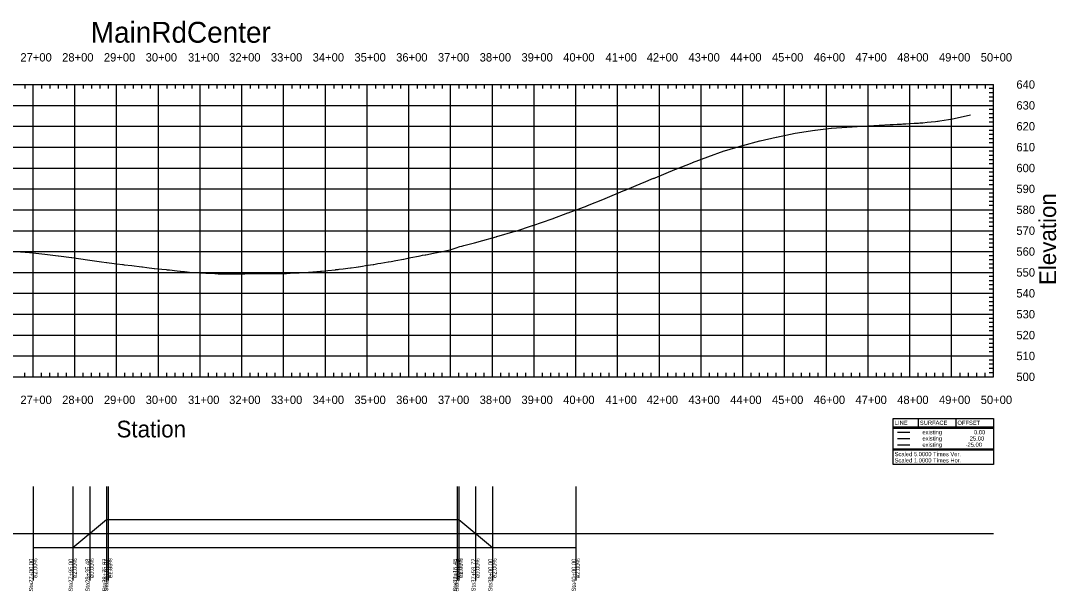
# Model space of a CAD drawing. Extents: x 708103 to 717568, y 374476 to 378707.
# Drawn here: x 709989 to 712470, y 374476 to 375842 of the extents above; entities that cross this region are included whole.
import ezdxf

# ---------------------------------------------------------------- set-up
doc = ezdxf.new("R2010")
doc.units = 0
for name, color, linetype in [('1', 7, 'Continuous'), ('54', 7, 'Continuous'), ('61', 7, 'Continuous'), ('63', 7, 'Continuous'), ('Existing', 7, 'Continuous')]:
    doc.layers.add(name, color=color, linetype=linetype)

msp = doc.modelspace()

# ---------------------------------------------------------------- linework, layer by layer
for points in [[(710019, 374581.2), (710114, 374581.2), (710195, 374648.4), (711038.5, 374648.4), (711119, 374581.2), (711319, 374581.2)], [(708319, 374614.8), (712319, 374614.8)], [(710019, 374581.2), (711319, 374581.2)]]:
    msp.add_lwpolyline(points)
at = {"layer": '54'}
for points in [[(710019, 374727.3), (710019, 374502.3)], [(710114, 374727.3), (710114, 374502.3)], [(710154.5, 374727.3), (710154.5, 374502.3)], [(710195, 374727.3), (710195, 374502.3)], [(710199, 374727.3), (710199, 374502.3)], [(711034.5, 374727.3), (711034.5, 374502.3)], [(711038.5, 374727.3), (711038.5, 374502.3)], [(711078.7, 374727.3), (711078.7, 374502.3)], [(711119, 374727.3), (711119, 374502.3)], [(711319, 374727.3), (711319, 374502.3)]]:
    msp.add_lwpolyline(points, dxfattribs=at)
at = {"layer": '61'}
for p, q in [((708319, 375689.8), (712319, 375689.8)), ((709999, 375689.8), (709999, 375679.8)), ((710019, 374989.8), (710019, 375689.8)), ((710039, 375689.8), (710039, 375679.8)), ((710059, 375689.8), (710059, 375679.8)), ((710079, 375689.8), (710079, 375679.8)), ((710099, 375689.8), (710099, 375679.8)), ((710119, 374989.8), (710119, 375689.8)), ((710139, 375689.8), (710139, 375679.8)), ((710159, 375689.8), (710159, 375679.8)), ((710179, 375689.8), (710179, 375679.8)), ((710199, 375689.8), (710199, 375679.8)), ((710219, 374989.8), (710219, 375689.8)), ((710239, 375689.8), (710239, 375679.8)), ((710259, 375689.8), (710259, 375679.8)), ((710279, 375689.8), (710279, 375679.8)), ((710299, 375689.8), (710299, 375679.8)), ((710319, 374989.8), (710319, 375689.8)), ((710339, 375689.8), (710339, 375679.8)), ((710359, 375689.8), (710359, 375679.8)), ((710379, 375689.8), (710379, 375679.8)), ((710399, 375689.8), (710399, 375679.8)), ((710419, 374989.8), (710419, 375689.8)), ((710439, 375689.8), (710439, 375679.8)), ((710459, 375689.8), (710459, 375679.8)), ((710479, 375689.8), (710479, 375679.8)), ((710499, 375689.8), (710499, 375679.8)), ((710519, 374989.8), (710519, 375689.8)), ((710539, 375689.8), (710539, 375679.8)), ((710559, 375689.8), (710559, 375679.8)), ((710579, 375689.8), (710579, 375679.8)), ((710599, 375689.8), (710599, 375679.8)), ((710619, 374989.8), (710619, 375689.8)), ((710639, 375689.8), (710639, 375679.8)), ((710659, 375689.8), (710659, 375679.8)), ((710679, 375689.8), (710679, 375679.8)), ((710699, 375689.8), (710699, 375679.8)), ((710719, 374989.8), (710719, 375689.8)), ((710739, 375689.8), (710739, 375679.8)), ((710759, 375689.8), (710759, 375679.8)), ((710779, 375689.8), (710779, 375679.8)), ((710799, 375689.8), (710799, 375679.8)), ((710819, 374989.8), (710819, 375689.8)), ((710839, 375689.8), (710839, 375679.8)), ((710859, 375689.8), (710859, 375679.8)), ((710879, 375689.8), (710879, 375679.8)), ((710899, 375689.8), (710899, 375679.8)), ((710919, 374989.8), (710919, 375689.8)), ((710939, 375689.8), (710939, 375679.8)), ((710959, 375689.8), (710959, 375679.8)), ((710979, 375689.8), (710979, 375679.8)), ((710999, 375689.8), (710999, 375679.8)), ((711019, 374989.8), (711019, 375689.8)), ((711039, 375689.8), (711039, 375679.8)), ((711059, 375689.8), (711059, 375679.8)), ((711079, 375689.8), (711079, 375679.8)), ((711099, 375689.8), (711099, 375679.8)), ((711119, 374989.8), (711119, 375689.8)), ((711139, 375689.8), (711139, 375679.8)), ((711159, 375689.8), (711159, 375679.8)), ((711179, 375689.8), (711179, 375679.8)), ((711199, 375689.8), (711199, 375679.8)), ((711219, 374989.8), (711219, 375689.8)), ((711239, 375689.8), (711239, 375679.8)), ((711259, 375689.8), (711259, 375679.8)), ((711279, 375689.8), (711279, 375679.8)), ((711299, 375689.8), (711299, 375679.8)), ((711319, 374989.8), (711319, 375689.8)), ((711339, 375689.8), (711339, 375679.8)), ((711359, 375689.8), (711359, 375679.8)), ((711379, 375689.8), (711379, 375679.8)), ((711399, 375689.8), (711399, 375679.8)), ((711419, 374989.8), (711419, 375689.8)), ((711439, 375689.8), (711439, 375679.8)), ((711459, 375689.8), (711459, 375679.8)), ((711479, 375689.8), (711479, 375679.8)), ((711499, 375689.8), (711499, 375679.8)), ((711519, 374989.8), (711519, 375689.8)), ((711539, 375689.8), (711539, 375679.8)), ((711559, 375689.8), (711559, 375679.8)), ((711579, 375689.8), (711579, 375679.8)), ((711599, 375689.8), (711599, 375679.8)), ((711619, 374989.8), (711619, 375689.8)), ((711639, 375689.8), (711639, 375679.8)), ((711659, 375689.8), (711659, 375679.8)), ((711679, 375689.8), (711679, 375679.8)), ((711699, 375689.8), (711699, 375679.8)), ((711719, 374989.8), (711719, 375689.8)), ((711739, 375689.8), (711739, 375679.8)), ((711759, 375689.8), (711759, 375679.8)), ((711779, 375689.8), (711779, 375679.8)), ((711799, 375689.8), (711799, 375679.8)), ((711819, 374989.8), (711819, 375689.8)), ((711839, 375689.8), (711839, 375679.8)), ((711859, 375689.8), (711859, 375679.8)), ((711879, 375689.8), (711879, 375679.8)), ((711899, 375689.8), (711899, 375679.8)), ((711919, 374989.8), (711919, 375689.8)), ((711939, 375689.8), (711939, 375679.8)), ((711959, 375689.8), (711959, 375679.8)), ((711979, 375689.8), (711979, 375679.8)), ((711999, 375689.8), (711999, 375679.8)), ((712019, 374989.8), (712019, 375689.8)), ((712039, 375689.8), (712039, 375679.8)), ((712059, 375689.8), (712059, 375679.8)), ((712079, 375689.8), (712079, 375679.8)), ((712099, 375689.8), (712099, 375679.8)), ((712119, 374989.8), (712119, 375689.8)), ((712139, 375689.8), (712139, 375679.8)), ((712159, 375689.8), (712159, 375679.8)), ((712179, 375689.8), (712179, 375679.8)), ((712199, 375689.8), (712199, 375679.8)), ((712219, 374989.8), (712219, 375689.8)), ((712239, 375689.8), (712239, 375679.8)), ((712259, 375689.8), (712259, 375679.8)), ((712279, 375689.8), (712279, 375679.8)), ((712299, 375689.8), (712299, 375679.8)), ((712319, 374989.8), (712319, 375689.8)), ((712319, 375679.8), (712309, 375679.8)), ((712319, 375669.8), (712309, 375669.8)), ((712319, 375659.8), (712309, 375659.8)), ((708319, 375639.8), (712319, 375639.8)), ((712319, 375649.8), (712309, 375649.8)), ((712319, 375629.8), (712309, 375629.8)), ((712319, 375619.8), (712309, 375619.8)), ((712319, 375609.8), (712309, 375609.8)), ((708319, 375589.8), (712319, 375589.8)), ((712319, 375599.8), (712309, 375599.8)), ((712319, 375579.8), (712309, 375579.8)), ((712319, 375569.8), (712309, 375569.8)), ((712319, 375559.8), (712309, 375559.8)), ((708319, 375539.8), (712319, 375539.8)), ((712319, 375549.8), (712309, 375549.8)), ((712319, 375529.8), (712309, 375529.8)), ((712319, 375519.8), (712309, 375519.8)), ((712319, 375509.8), (712309, 375509.8)), ((708319, 375489.8), (712319, 375489.8)), ((712319, 375499.8), (712309, 375499.8)), ((712319, 375479.8), (712309, 375479.8)), ((712319, 375469.8), (712309, 375469.8)), ((712319, 375459.8), (712309, 375459.8)), ((708319, 375439.8), (712319, 375439.8)), ((712319, 375449.8), (712309, 375449.8)), ((712319, 375429.8), (712309, 375429.8)), ((712319, 375419.8), (712309, 375419.8)), ((712319, 375409.8), (712309, 375409.8)), ((708319, 375389.8), (712319, 375389.8)), ((712319, 375399.8), (712309, 375399.8)), ((712319, 375379.8), (712309, 375379.8)), ((712319, 375369.8), (712309, 375369.8)), ((712319, 375359.8), (712309, 375359.8)), ((708319, 375339.8), (712319, 375339.8)), ((712319, 375349.8), (712309, 375349.8)), ((712319, 375329.8), (712309, 375329.8)), ((712319, 375319.8), (712309, 375319.8)), ((712319, 375309.8), (712309, 375309.8)), ((708319, 375289.8), (712319, 375289.8)), ((712319, 375299.8), (712309, 375299.8)), ((712319, 375279.8), (712309, 375279.8)), ((712319, 375269.8), (712309, 375269.8)), ((712319, 375259.8), (712309, 375259.8)), ((708319, 375239.8), (712319, 375239.8)), ((712319, 375249.8), (712309, 375249.8)), ((712319, 375229.8), (712309, 375229.8)), ((712319, 375219.8), (712309, 375219.8)), ((712319, 375209.8), (712309, 375209.8)), ((708319, 375189.8), (712319, 375189.8)), ((712319, 375199.8), (712309, 375199.8)), ((712319, 375179.8), (712309, 375179.8)), ((712319, 375169.8), (712309, 375169.8)), ((708319, 375139.8), (712319, 375139.8)), ((712319, 375159.8), (712309, 375159.8)), ((712319, 375149.8), (712309, 375149.8)), ((712319, 375129.8), (712309, 375129.8)), ((712319, 375119.8), (712309, 375119.8)), ((708319, 375089.8), (712319, 375089.8)), ((712319, 375109.8), (712309, 375109.8)), ((712319, 375099.8), (712309, 375099.8)), ((712319, 375079.8), (712309, 375079.8)), ((712319, 375069.8), (712309, 375069.8)), ((708319, 375039.8), (712319, 375039.8)), ((712319, 375059.8), (712309, 375059.8)), ((712319, 375049.8), (712309, 375049.8)), ((712319, 375029.8), (712309, 375029.8)), ((712319, 375019.8), (712309, 375019.8)), ((708319, 374989.8), (712319, 374989.8)), ((709999, 374989.8), (709999, 374999.8)), ((710039, 374989.8), (710039, 374999.8)), ((710059, 374989.8), (710059, 374999.8)), ((710079, 374989.8), (710079, 374999.8)), ((710099, 374989.8), (710099, 374999.8)), ((710139, 374989.8), (710139, 374999.8)), ((710159, 374989.8), (710159, 374999.8)), ((710179, 374989.8), (710179, 374999.8)), ((710199, 374989.8), (710199, 374999.8)), ((710239, 374989.8), (710239, 374999.8)), ((710259, 374989.8), (710259, 374999.8)), ((710279, 374989.8), (710279, 374999.8)), ((710299, 374989.8), (710299, 374999.8)), ((710339, 374989.8), (710339, 374999.8)), ((710359, 374989.8), (710359, 374999.8)), ((710379, 374989.8), (710379, 374999.8)), ((710399, 374989.8), (710399, 374999.8)), ((710439, 374989.8), (710439, 374999.8)), ((710459, 374989.8), (710459, 374999.8)), ((710479, 374989.8), (710479, 374999.8)), ((710499, 374989.8), (710499, 374999.8)), ((710539, 374989.8), (710539, 374999.8)), ((710559, 374989.8), (710559, 374999.8)), ((710579, 374989.8), (710579, 374999.8)), ((710599, 374989.8), (710599, 374999.8)), ((710639, 374989.8), (710639, 374999.8)), ((710659, 374989.8), (710659, 374999.8)), ((710679, 374989.8), (710679, 374999.8)), ((710699, 374989.8), (710699, 374999.8)), ((710739, 374989.8), (710739, 374999.8)), ((710759, 374989.8), (710759, 374999.8)), ((710779, 374989.8), (710779, 374999.8)), ((710799, 374989.8), (710799, 374999.8)), ((710839, 374989.8), (710839, 374999.8)), ((710859, 374989.8), (710859, 374999.8)), ((710879, 374989.8), (710879, 374999.8)), ((710899, 374989.8), (710899, 374999.8)), ((710939, 374989.8), (710939, 374999.8)), ((710959, 374989.8), (710959, 374999.8)), ((710979, 374989.8), (710979, 374999.8)), ((710999, 374989.8), (710999, 374999.8)), ((711039, 374989.8), (711039, 374999.8)), ((711059, 374989.8), (711059, 374999.8)), ((711079, 374989.8), (711079, 374999.8)), ((711099, 374989.8), (711099, 374999.8)), ((711139, 374989.8), (711139, 374999.8)), ((711159, 374989.8), (711159, 374999.8)), ((711179, 374989.8), (711179, 374999.8)), ((711199, 374989.8), (711199, 374999.8)), ((711239, 374989.8), (711239, 374999.8)), ((711259, 374989.8), (711259, 374999.8)), ((711279, 374989.8), (711279, 374999.8)), ((711299, 374989.8), (711299, 374999.8)), ((711339, 374989.8), (711339, 374999.8)), ((711359, 374989.8), (711359, 374999.8)), ((711379, 374989.8), (711379, 374999.8)), ((711399, 374989.8), (711399, 374999.8)), ((711439, 374989.8), (711439, 374999.8)), ((711459, 374989.8), (711459, 374999.8)), ((711479, 374989.8), (711479, 374999.8)), ((711499, 374989.8), (711499, 374999.8)), ((711539, 374989.8), (711539, 374999.8)), ((711559, 374989.8), (711559, 374999.8)), ((711579, 374989.8), (711579, 374999.8)), ((711599, 374989.8), (711599, 374999.8)), ((711639, 374989.8), (711639, 374999.8)), ((711659, 374989.8), (711659, 374999.8)), ((711679, 374989.8), (711679, 374999.8)), ((711699, 374989.8), (711699, 374999.8)), ((711739, 374989.8), (711739, 374999.8)), ((711759, 374989.8), (711759, 374999.8)), ((711779, 374989.8), (711779, 374999.8)), ((711799, 374989.8), (711799, 374999.8)), ((711839, 374989.8), (711839, 374999.8)), ((711859, 374989.8), (711859, 374999.8)), ((711879, 374989.8), (711879, 374999.8)), ((711899, 374989.8), (711899, 374999.8)), ((711939, 374989.8), (711939, 374999.8)), ((711959, 374989.8), (711959, 374999.8)), ((711979, 374989.8), (711979, 374999.8)), ((711999, 374989.8), (711999, 374999.8)), ((712039, 374989.8), (712039, 374999.8)), ((712059, 374989.8), (712059, 374999.8)), ((712079, 374989.8), (712079, 374999.8)), ((712099, 374989.8), (712099, 374999.8)), ((712139, 374989.8), (712139, 374999.8)), ((712159, 374989.8), (712159, 374999.8)), ((712179, 374989.8), (712179, 374999.8)), ((712199, 374989.8), (712199, 374999.8)), ((712239, 374989.8), (712239, 374999.8)), ((712259, 374989.8), (712259, 374999.8)), ((712279, 374989.8), (712279, 374999.8)), ((712299, 374989.8), (712299, 374999.8)), ((712319, 375009.8), (712309, 375009.8)), ((712319, 374999.8), (712309, 374999.8)), ((712139, 374889.8), (712139, 374869.8)), ((712229, 374889.8), (712229, 374869.8)), ((712079, 374869.8), (712319, 374869.8)), ((712079, 374867.3), (712319, 374867.3)), ((712079, 374817.3), (712319, 374817.3)), ((712079, 374814.8), (712319, 374814.8))]:
    msp.add_line(p, q, dxfattribs=at)
msp.add_lwpolyline([(712079, 374889.8), (712319, 374889.8), (712319, 374779.8), (712079, 374779.8)], close=True, dxfattribs=at)
at = {"layer": '63'}
for p, q in [((712089, 374842.3), (712119, 374842.3)), ((712089, 374827.3), (712119, 374827.3))]:
    msp.add_line(p, q, dxfattribs=at)
at = {"layer": 'Existing'}
msp.add_line((712089, 374857.3), (712119, 374857.3), dxfattribs=at)
msp.add_lwpolyline([(709978.4, 375290.3), (710010.5, 375287.5), (710010.8, 375287.4), (710047.4, 375283.3), (710047.5, 375283.3), (710079.1, 375279.5), (710079.5, 375279.5), (710111, 375275.3), (710112, 375275.2), (710149.4, 375269.9), (710149.5, 375269.9), (710149.6, 375269.9), (710183.1, 375265.3), (710194.5, 375263.8), (710195.3, 375263.7), (710201.2, 375262.9), (710219.2, 375260.6), (710233, 375258.9), (710233.5, 375258.8), (710234, 375258.8), (710235, 375258.7), (710237.3, 375258.4), (710255.4, 375256.1), (710260.9, 375255.4), (710273.4, 375253.7), (710279.4, 375253), (710280.4, 375252.8), (710280.5, 375253), (710280.9, 375252.9), (710291.5, 375251.5), (710308.6, 375249.2), (710309.6, 375249.1), (710309.8, 375249.1), (710327.6, 375247.5), (710338.1, 375246.6), (710340.3, 375246.4), (710340.4, 375246.4), (710344.2, 375245.9), (710345.7, 375245.8), (710363.8, 375243.7), (710371.6, 375242.8), (710372.1, 375242.8), (710378.5, 375242.2), (710381.8, 375241.8), (710399.9, 375240), (710401.2, 375239.9), (710402.4, 375239.8), (710418, 375238.9), (710432.4, 375238), (710432.7, 375238), (710436, 375237.8), (710454.1, 375237), (710462.3, 375236.7), (710463.2, 375236.6), (710472.2, 375236.6), (710490.2, 375236.6), (710496.4, 375236.6), (710497.6, 375236.6), (710508.3, 375236.7), (710526.4, 375236.8), (710528.9, 375236.9), (710530.1, 375236.9), (710544.4, 375236.9), (710562.1, 375237), (710562.5, 375237), (710562.9, 375237), (710580.6, 375237.2), (710590.2, 375237.3), (710590.8, 375237.3), (710598.6, 375237.4), (710616.7, 375237.4), (710622.2, 375237.5), (710624, 375237.5), (710625.8, 375237.6), (710634.8, 375238), (710652.8, 375238.8), (710655.7, 375238.9), (710655.9, 375239), (710670.9, 375239.8), (710674, 375239.9), (710678.6, 375240.3), (710680.9, 375240.4), (710683.8, 375240.6), (710689, 375241), (710707.1, 375242.5), (710707.8, 375242.5), (710709.4, 375242.6), (710725.1, 375244.3), (710743.2, 375246.3), (710744.2, 375246.5), (710749.6, 375246.8), (710751.8, 375247.3), (710761.3, 375248.2), (710761.4, 375248.2), (710772.8, 375250.1), (710779, 375250.6), (710779.3, 375250.7), (710780.5, 375251), (710793.1, 375252.2), (710797.4, 375252.9), (710798, 375253), (710808.3, 375255.1), (710815.5, 375256.1), (710833.5, 375258.9), (710834.7, 375259), (710838.3, 375259.7), (710844.9, 375260.9), (710851.6, 375262.1), (710869.7, 375265.1), (710870, 375265.2), (710870.3, 375265.2), (710876.7, 375266.3), (710887.7, 375268.3), (710905.8, 375271.6), (710906.8, 375271.8), (710913, 375273), (710916.2, 375273.6), (710916.3, 375273.7), (710917.1, 375274), (710923.9, 375275.3), (710941.9, 375278.8), (710946.3, 375279.7), (710952, 375280.9), (710958, 375282), (710958.6, 375282), (710960, 375282.3), (710978.1, 375285.7), (710987, 375287.5), (710993.8, 375289), (710996.1, 375289.3), (710998.5, 375289.7), (711014.2, 375293.4), (711018.1, 375294.3), (711018.7, 375294.3), (711019.3, 375294.4), (711020.6, 375295), (711032.3, 375298.8), (711041.2, 375301.6), (711046.1, 375302.9), (711050.3, 375304), (711076.5, 375310.8), (711085.1, 375313), (711087.2, 375313.6), (711128.4, 375325.3), (711129, 375325.5), (711129, 375325.5), (711129.7, 375325.7), (711173.9, 375338.6), (711174.5, 375338.8), (711175, 375339), (711215, 375351.8), (711215.1, 375351.8), (711215.9, 375352.1), (711262, 375368.2), (711300, 375382.6), (711300.6, 375382.8), (711346, 375399.6), (711346.3, 375399.7), (711346.6, 375399.8), (711387.3, 375415.8), (711389, 375416.5), (711432.5, 375435), (711434.9, 375436), (711437.1, 375437.1), (711478.4, 375454.3), (711480.7, 375455.3), (711504.8, 375465.3), (711505.2, 375465.5), (711505.6, 375465.1), (711508.5, 375466.3), (711556, 375485.9), (711558.6, 375486.9), (711597.7, 375502.3), (711598.6, 375502.7), (711634.9, 375516.6), (711634.9, 375516.6), (711635, 375516.6), (711635, 375516.7), (711635.2, 375516.7), (711635.4, 375516.8), (711635.4, 375516.8), (711635.4, 375516.8), (711635.4, 375516.8), (711674.4, 375530.6), (711674.8, 375530.7), (711675, 375530.8), (711701.7, 375538.9), (711718.2, 375543.9), (711718.6, 375544), (711719, 375544.1), (711759.8, 375554.5), (711760.3, 375554.7), (711798.6, 375563.3), (711799.1, 375563.4), (711844.4, 375572.9), (711891.1, 375580.5), (711891.5, 375580.6), (711891.9, 375580.6), (711930.8, 375585.6), (711930.9, 375585.6), (711967.9, 375587.8), (711968.2, 375587.8), (712005.7, 375590.1), (712006.5, 375590.1), (712006.6, 375590.1), (712045.1, 375592.3), (712045.6, 375592.5), (712045.6, 375592.5), (712071.9, 375593.8), (712071.9, 375593.8), (712071.9, 375593.8), (712078.5, 375594.2), (712088.7, 375594.7), (712098.9, 375595.2), (712101.9, 375595.4), (712102, 375595.4), (712103, 375595.4), (712109.1, 375595.7), (712119.3, 375596.3), (712129.5, 375596.8), (712139.7, 375597.4), (712143, 375597.6), (712144.5, 375597.7), (712149.9, 375598.2), (712160.1, 375599.3), (712170.3, 375600.3), (712180.5, 375601.4), (712185.4, 375601.9), (712186.7, 375602), (712190.7, 375602.7), (712200.9, 375604.3), (712211.1, 375605.9), (712221.3, 375607.4), (712224.9, 375608), (712263.9, 375616.8)], dxfattribs=at)

# ---------------------------------------------------------------- texts
at = {"layer": '1'}
for s, height, p in [('MainRdCenter', 50, (710157.2, 375789.8)), ('Station', 40, (710218.8, 374844.8)), (' LINE ', 10, (712079, 374874.8)), (' SURFACE ', 10, (712139, 374874.8)), ('existing', 10, (712149, 374852.3)), (' OFFSET ', 10, (712229, 374874.8)), ('0.00', 10, (712272.4, 374852.3)), ('existing', 10, (712149, 374837.3)), ('25.00', 10, (712262.4, 374837.3)), ('existing', 10, (712149, 374822.3)), ('-25.00', 10, (712252.4, 374822.3)), ('Scaled 5.0000 Times Ver.', 10, (712082.4, 374799.8)), ('Scaled 1.0000 Times Hor.', 10, (712082.4, 374784.8))]:
    msp.add_text(s, height=height, dxfattribs=at).set_placement(p)
at = {"layer": '54'}
for s, p in [('Sta27+00.00', (710019, 374475.9)), ('e2.00%', (710029, 374508.3)), ('Sta27+95.00', (710114, 374475.9)), ('e2.00%', (710124, 374508.3)), ('Sta28+35.48', (710154.5, 374475.8)), ('e0.00%', (710164.5, 374508.3)), ('Sta28+75.97', (710194.9, 374475.9)), ('Sta28+79.97', (710198.9, 374475.9)), ('e2.00%', (710205, 374508.3)), ('e2.00%', (710209, 374508.3)), ('Sta37+15.45', (711034.4, 374475.8)), ('Sta37+19.45', (711038.4, 374475.8)), ('e2.00%', (711044.5, 374508.3)), ('e2.00%', (711048.5, 374508.3)), ('Sta37+59.72', (711078.7, 374476)), ('e0.00%', (711088.8, 374508.3)), ('Sta38+00.00', (711119, 374475.9)), ('e2.00%', (711129, 374508.3)), ('Sta40+00.00', (711319, 374475.9)), ('e2.00%', (711329, 374508.3))]:
    msp.add_text(s, height=10, rotation=90, dxfattribs=at).set_placement(p)
at = {"layer": '61'}
for s, p in [('27+00', (709988.6, 375744.8)), ('28+00', (710088.6, 375744.8)), ('29+00', (710188.6, 375744.8)), ('30+00', (710288.6, 375744.8)), ('31+00', (710390.1, 375744.8)), ('32+00', (710488.6, 375744.8)), ('33+00', (710588.6, 375744.8)), ('34+00', (710688.6, 375744.8)), ('35+00', (710788.6, 375744.8)), ('36+00', (710888.6, 375744.8)), ('37+00', (710988.6, 375744.8)), ('38+00', (711088.6, 375744.8)), ('39+00', (711188.6, 375744.8)), ('40+00', (711288.6, 375744.8)), ('41+00', (711390.1, 375744.8)), ('42+00', (711488.6, 375744.8)), ('43+00', (711588.6, 375744.8)), ('44+00', (711688.6, 375744.8)), ('45+00', (711788.6, 375744.8)), ('46+00', (711888.6, 375744.8)), ('47+00', (711988.6, 375744.8)), ('48+00', (712088.6, 375744.8)), ('49+00', (712188.6, 375744.8)), ('50+00', (712288.6, 375744.8)), ('640', (712374, 375679.8)), ('640', (712374, 375679.8)), ('630', (712374, 375629.8)), ('620', (712374, 375579.8)), ('610', (712374, 375529.8)), ('600', (712374, 375479.8)), ('590', (712374, 375429.8)), ('580', (712374, 375379.8)), ('570', (712374, 375329.8)), ('560', (712374, 375279.8)), ('550', (712374, 375229.8)), ('540', (712374, 375179.8)), ('530', (712374, 375129.8)), ('520', (712374, 375079.8)), ('510', (712374, 375029.8)), ('500', (712374, 374979.8)), ('27+00', (709988.6, 374924.8)), ('28+00', (710088.6, 374924.8)), ('29+00', (710188.6, 374924.8)), ('30+00', (710288.6, 374924.8)), ('31+00', (710390.1, 374924.8)), ('32+00', (710488.6, 374924.8)), ('33+00', (710588.6, 374924.8)), ('34+00', (710688.6, 374924.8)), ('35+00', (710788.6, 374924.8)), ('36+00', (710888.6, 374924.8)), ('37+00', (710988.6, 374924.8)), ('38+00', (711088.6, 374924.8)), ('39+00', (711188.6, 374924.8)), ('40+00', (711288.6, 374924.8)), ('41+00', (711390.1, 374924.8)), ('42+00', (711488.6, 374924.8)), ('43+00', (711588.6, 374924.8)), ('44+00', (711688.6, 374924.8)), ('45+00', (711788.6, 374924.8)), ('46+00', (711888.6, 374924.8)), ('47+00', (711988.6, 374924.8)), ('48+00', (712088.6, 374924.8)), ('49+00', (712188.6, 374924.8)), ('50+00', (712288.6, 374924.8))]:
    msp.add_text(s, height=20, dxfattribs=at).set_placement(p)
msp.add_text('Elevation', height=40, rotation=90, dxfattribs=at).set_placement((712469, 375209.6))

doc.saveas('drawing.dxf')
